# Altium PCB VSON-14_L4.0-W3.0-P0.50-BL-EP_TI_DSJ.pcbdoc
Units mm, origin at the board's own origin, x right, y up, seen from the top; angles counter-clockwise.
Board outline 17.1 x 16.73 mm, 2 copper layers (Top Layer, Bottom Layer), stack 0 mm thick; 1 components, 0 nets, 15 pads, 0 vias.
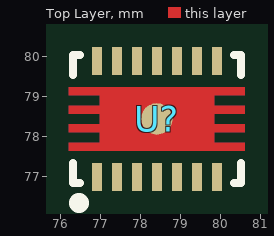
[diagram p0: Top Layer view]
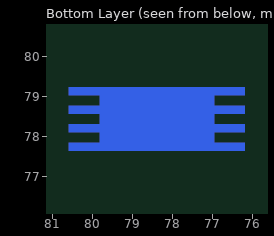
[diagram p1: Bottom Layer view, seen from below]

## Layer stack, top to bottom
Top Layer: signal copper (thickness not stored)
Bottom Layer: signal copper (thickness not stored)

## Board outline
86.95,69.85 69.85,69.85 69.85,86.576 86.95,86.576

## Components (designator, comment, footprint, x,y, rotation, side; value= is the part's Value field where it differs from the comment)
U? "" VSON-14_L4.0-W3.0-P0.50-BL-EP_TI_DSJ 78.4,78.426 r0 top

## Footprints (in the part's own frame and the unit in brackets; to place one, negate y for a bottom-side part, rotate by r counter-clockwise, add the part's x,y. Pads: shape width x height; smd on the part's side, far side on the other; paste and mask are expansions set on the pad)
VSON-14_L4.0-W3.0-P0.50-BL-EP_TI_DSJ [mm]
  rect 0.25x0.7 smd: 1(-1.5,-1.45) 2(-1,-1.45) 3(-0.5,-1.45) 4(0,-1.45) 5(0.5,-1.45) 6(1,-1.45) 7(1.5,-1.45) 8(1.5,1.45) 9(1,1.45) 10(0.5,1.45) 11(0,1.45) 12(-0.5,1.45) 13(-1,1.45) 14(-1.5,1.45)
  round 0.79 smd: 15(0,0)
  Top Layer region: -2.2,0.79 -2.2,0.59 -1.43,0.59 -1.43,0.33 -2.2,0.33 -2.2,0.13 -1.43,0.13 -1.43,-0.13 -2.2,-0.13 -2.2,-0.33 -1.43,-0.33 -1.43,-0.59 -2.2,-0.59 -2.2,-0.79 2.2,-0.79 2.2,-0.59 1.43,-0.59 1.43,-0.33 2.2,-0.33 2.2,-0.13 1.43,-0.13 1.43,0.13 2.2,0.13 2.2,0.33 1.43,0.33 1.43,0.59 2.2,0.59 2.2,0.79
  Bottom Layer region: -2.2,0.79 -2.2,0.59 -1.43,0.59 -1.43,0.33 -2.2,0.33 -2.2,0.13 -1.43,0.13 -1.43,-0.13 -2.2,-0.13 -2.2,-0.33 -1.43,-0.33 -1.43,-0.59 -2.2,-0.59 -2.2,-0.79 2.2,-0.79 2.2,-0.59 1.43,-0.59 1.43,-0.33 2.2,-0.33 2.2,-0.13 1.43,-0.13 1.43,0.13 2.2,0.13 2.2,0.33 1.43,0.33 1.43,0.59 2.2,0.59 2.2,0.79
  Multi-Layer region: -2.2,0.79 -2.2,0.59 -1.43,0.59 -1.43,0.33 -2.2,0.33 -2.2,0.13 -1.43,0.13 -1.43,-0.13 -2.2,-0.13 -2.2,-0.33 -1.43,-0.33 -1.43,-0.59 -2.2,-0.59 -2.2,-0.79 2.2,-0.79 2.2,-0.59 1.43,-0.59 1.43,-0.33 2.2,-0.33 2.2,-0.13 1.43,-0.13 1.43,0.13 2.2,0.13 2.2,0.33 1.43,0.33 1.43,0.59 2.2,0.59 2.2,0.79
  silkscreen extent -2.1,-2.23 2.1,1.6

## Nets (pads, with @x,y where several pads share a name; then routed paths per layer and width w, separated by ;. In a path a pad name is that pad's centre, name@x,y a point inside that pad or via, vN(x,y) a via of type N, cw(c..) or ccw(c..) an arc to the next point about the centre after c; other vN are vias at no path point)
pads on no net: U?.1 U?.2 U?.3 U?.4 U?.5 U?.6 U?.7 U?.8 U?.9 U?.10 U?.11 U?.12 U?.13 U?.14 U?.15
